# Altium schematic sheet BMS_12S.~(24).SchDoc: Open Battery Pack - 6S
size A3; Author: Morgane Vallée; Revision: 1.0; SheetNumber: 3; SheetTotal: 4
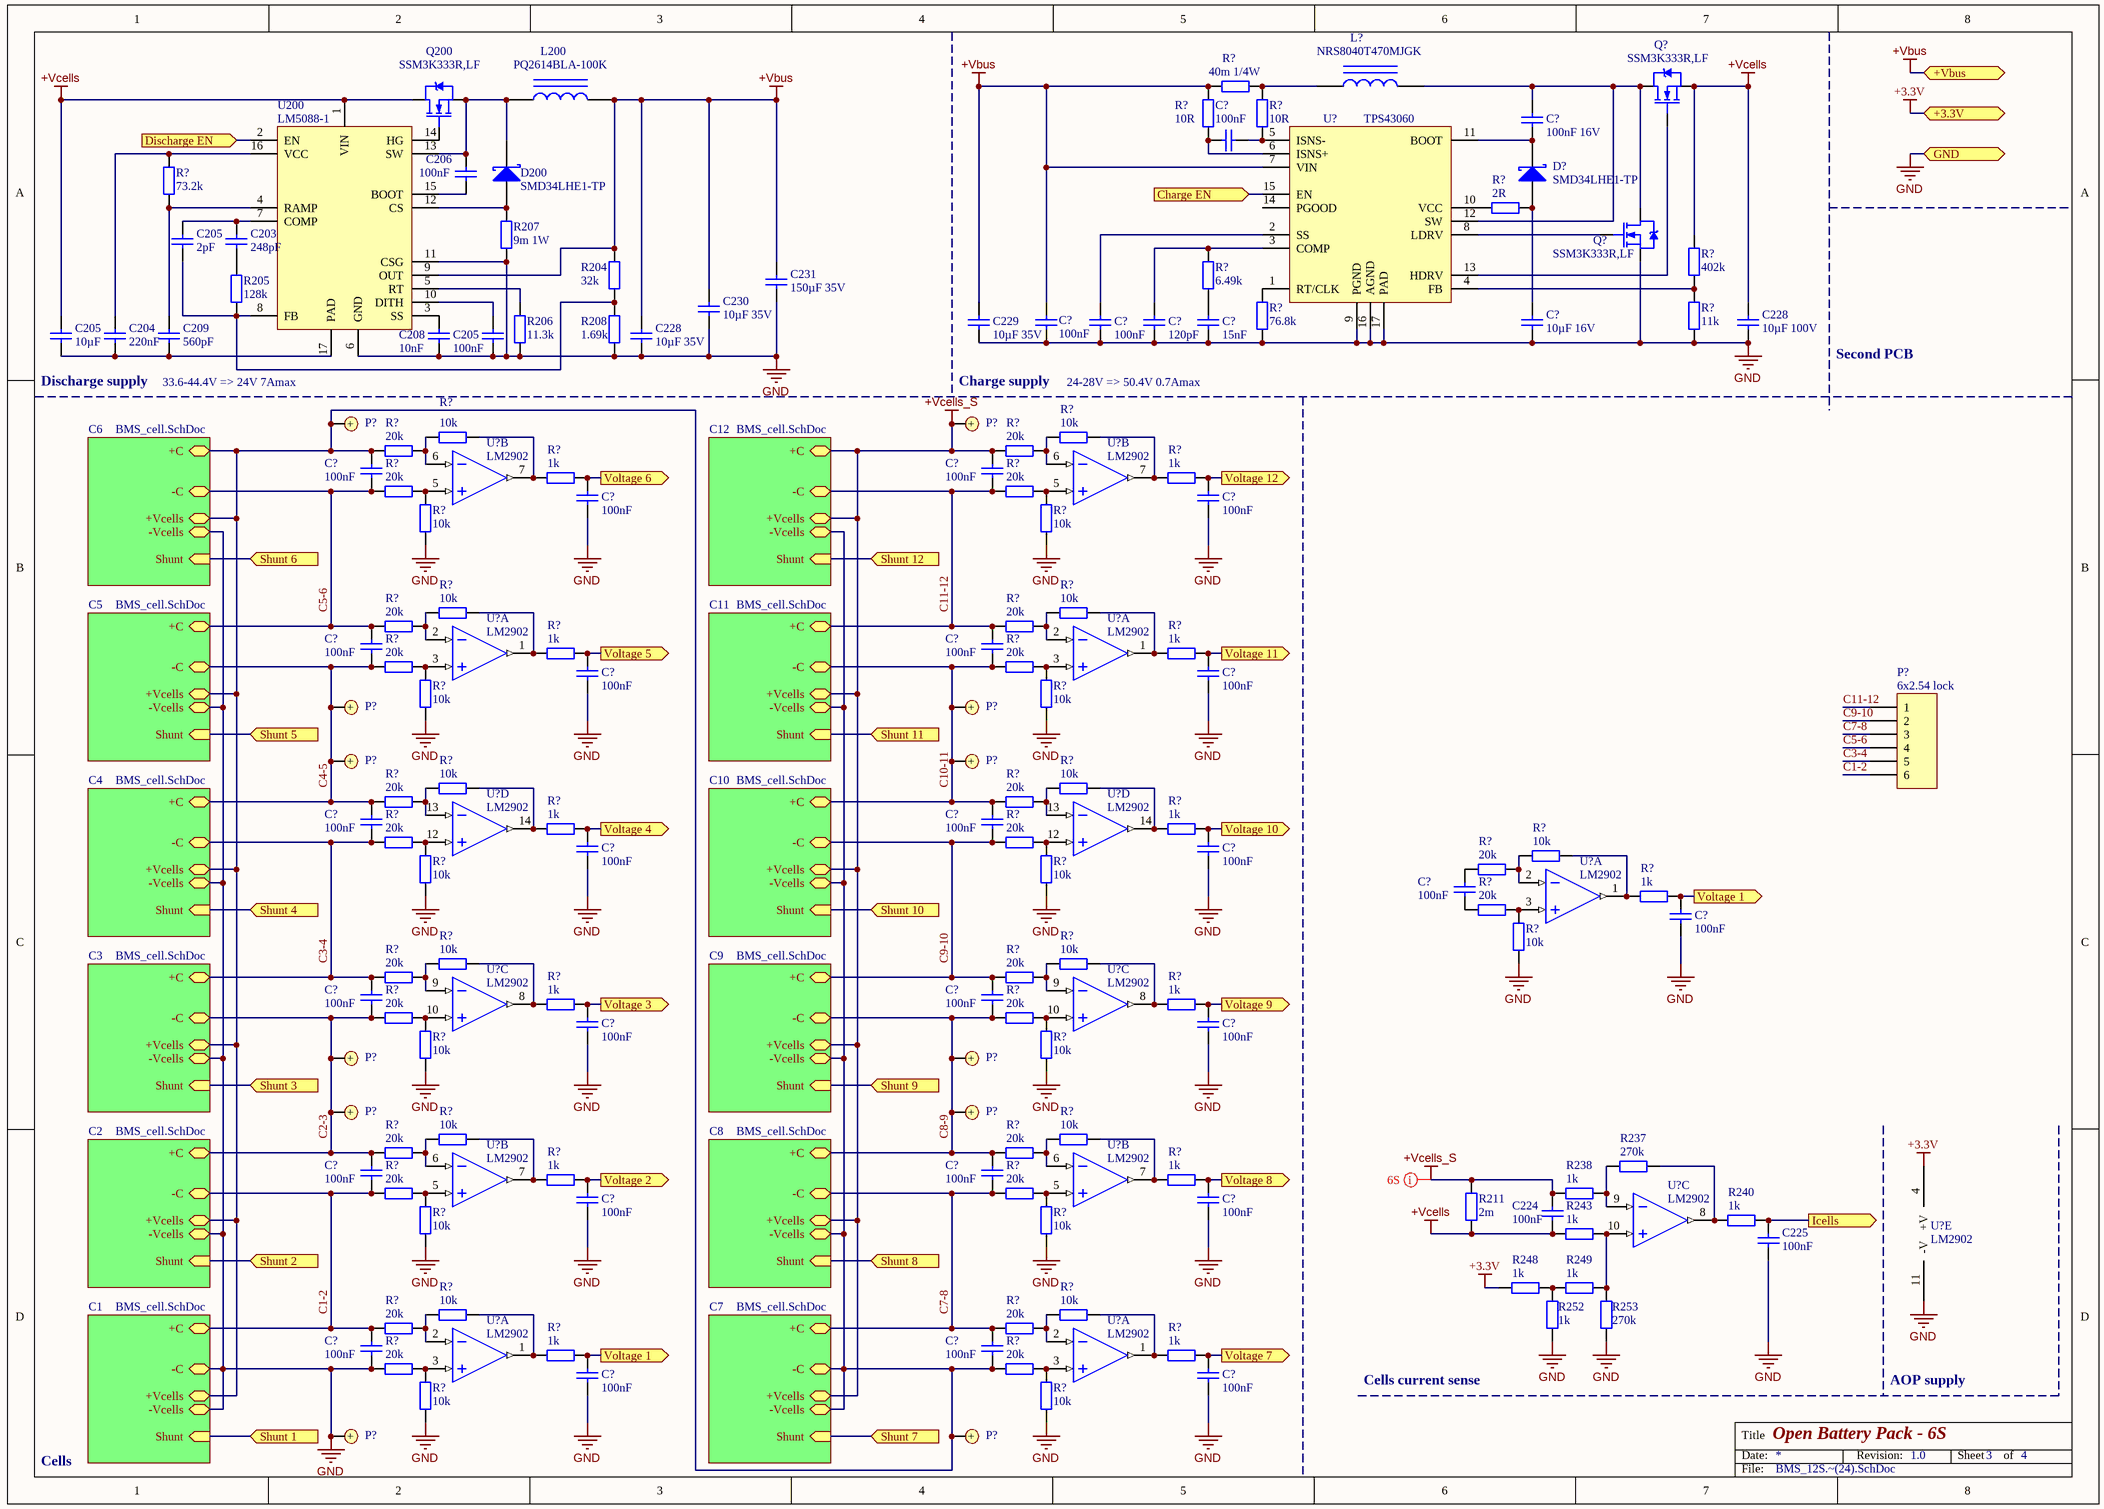
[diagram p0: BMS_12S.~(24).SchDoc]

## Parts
(Parts that share a designator on the sheet are numbered #1, #2 ... from top to bottom, then left to right.)
C203  248pF  [C0603]
C204  220nF  [C0603]
C205#1  2pF  [C0603]
C205#2  10µF  [C0603]
C205#3  100nF  [C0603]
C206  100nF  [C0603]
C208  10nF  [C0603]
C209  560pF  [C0603]
C224  100nF  [C0603]
C225  100nF  [C0603]
C228#1  10µF 100V  [C0603]
C228#2  10µF 35V  [C0603]
C229  10µF 35V  [C0603]
C230  10µF 35V  [C0603]
C231  150µF 35V  [C0603]
C?#1  100nF 16V  [C0603]
C?#2  100nF  [C0603]
C?#3  100nF  [C0603]
C?#4  120pF  [C0603]
C?#5  15nF  [C0603]
C?#6  10µF 16V  [C0805]
C?#7  100nF  [C0603]
C?#8  100nF  [C0603]
C?#9  100nF  [C0603]
C?#10  100nF  [C0603]
C?#11  100nF  [C0603]
C?#12  100nF  [C0603]
C?#13  100nF  [C0603]
C?#14  100nF  [C0603]
C?#15  100nF  [C0603]
C?#16  100nF  [C0603]
C?#17  100nF  [C0603]
C?#18  100nF  [C0603]
C?#19  100nF  [C0603]
C?#20  100nF  [C0603]
C?#21  100nF  [C0603]
C?#22  100nF  [C0603]
C?#23  100nF  [C0603]
C?#24  100nF  [C0603]
C?#25  100nF  [C0603]
C?#26  100nF  [C0603]
C?#27  100nF  [C0603]
C?#28  100nF  [C0603]
C?#29  100nF  [C0603]
C?#30  100nF  [C0603]
C?#31  100nF  [C0603]
C?#32  100nF  [C0603]
C?#33  100nF  [C0603]
D200  SMD34LHE1-TP  [SOD-123H]
D?  SMD34LHE1-TP  [SOD-123H]
L200  PQ2614BLA-100K  [SELF_SMD_8x8]
L?  NRS8040T470MJGK  [SELF_SMD_8x8]
P?#1  Bat+  [Keystone 241]  (value not drawn)
P?#2  Bat+  [Keystone 241]  (value not drawn)
P?#3  6x2.54 lock  [MOLEX KK 0022272061]
P?#4  Bat+  [Keystone 241]  (value not drawn)
P?#5  Bat+  [Keystone 241]  (value not drawn)
P?#6  Bat+  [Keystone 241]  (value not drawn)
P?#7  Bat+  [Keystone 241]  (value not drawn)
P?#8  Bat+  [Keystone 241]  (value not drawn)
P?#9  Bat+  [Keystone 241]  (value not drawn)
P?#10  Bat+  [Keystone 241]  (value not drawn)
P?#11  Bat+  [Keystone 241]  (value not drawn)
P?#12  Bat+  [Keystone 241]  (value not drawn)
P?#13  Bat+  [Keystone 241]  (value not drawn)
Q200  SSM3K333R,LF  [TI SOT-23-3 DBZ]
Q?#1  SSM3K333R,LF  [TI SOT-23-3 DBZ]
Q?#2  SSM3K333R,LF  [TI SOT-23-3 DBZ]
R204  32k  [R0603]
R205  128k  [R0603]
R206  11.3k  [R0603]
R207  9m 1W  [R1206]
R208  1.69k  [R0603]
R211  2m  [R1206]
R237  270k  [R0603]
R238  1k  [R0603]
R240  1k  [R0603]
R243  1k  [R0603]
R248  1k  [R0603]
R249  1k  [R0603]
R252  1k  [R0603]
R253  270k  [R0603]
R?#1  10R  [R0603]
R?#2  40m 1/4W  [R1206]
R?#3  10R  [R0603]
R?#4  73.2k  [R0603]
R?#5  2R  [R0603]
R?#6  402k  [R0603]
R?#7  6.49k  [R0603]
R?#8  76.8k  [R0603]
R?#9  11k  [R0603]
R?#10  10k  [R0603]
R?#11  10k  [R0603]
R?#12  20k  [R0603]
R?#13  20k  [R0603]
R?#14  1k  [R0603]
R?#15  1k  [R0603]
R?#16  20k  [R0603]
R?#17  10k  [R0603]
R?#18  20k  [R0603]
R?#19  10k  [R0603]
R?#20  10k  [R0603]
R?#21  10k  [R0603]
R?#22  20k  [R0603]
R?#23  20k  [R0603]
R?#24  1k  [R0603]
R?#25  1k  [R0603]
R?#26  20k  [R0603]
R?#27  10k  [R0603]
R?#28  20k  [R0603]
R?#29  10k  [R0603]
R?#30  10k  [R0603]
R?#31  10k  [R0603]
R?#32  20k  [R0603]
R?#33  20k  [R0603]
R?#34  1k  [R0603]
R?#35  1k  [R0603]
R?#36  10k  [R0603]
R?#37  20k  [R0603]
R?#38  10k  [R0603]
R?#39  20k  [R0603]
R?#40  10k  [R0603]
R?#41  20k  [R0603]
R?#42  1k  [R0603]
R?#43  20k  [R0603]
R?#44  10k  [R0603]
R?#45  10k  [R0603]
R?#46  10k  [R0603]
R?#47  20k  [R0603]
R?#48  20k  [R0603]
R?#49  1k  [R0603]
R?#50  1k  [R0603]
R?#51  20k  [R0603]
R?#52  10k  [R0603]
R?#53  20k  [R0603]
R?#54  10k  [R0603]
R?#55  10k  [R0603]
R?#56  10k  [R0603]
R?#57  20k  [R0603]
R?#58  20k  [R0603]
R?#59  1k  [R0603]
R?#60  1k  [R0603]
R?#61  20k  [R0603]
R?#62  10k  [R0603]
R?#63  20k  [R0603]
R?#64  10k  [R0603]
R?#65  10k  [R0603]
R?#66  10k  [R0603]
R?#67  20k  [R0603]
R?#68  20k  [R0603]
R?#69  1k  [R0603]
R?#70  1k  [R0603]
R?#71  20k  [R0603]
R?#72  10k  [R0603]
R?#73  20k  [R0603]
R?#74  10k  [R0603]
U200  LM5088-1  [TI MSOP-10 DGQ]
U?#1  TPS43060  [TI WQFN-16 RGH]
U?#2  LM2902  [Atmel SO-14 14S1]  (part B of 5)
U?#3  LM2902  [Atmel SO-14 14S1]  (part B of 5)
U?#4  LM2902  [Atmel SO-14 14S1]  (part A of 5)
U?#5  LM2902  [Atmel SO-14 14S1]  (part A of 5)
U?#6  LM2902  [Atmel SO-14 14S1]  (part D of 5)
U?#7  LM2902  [Atmel SO-14 14S1]  (part D of 5)
U?#8  LM2902  [Atmel SO-14 14S1]  (part A of 5)
U?#9  LM2902  [Atmel SO-14 14S1]  (part C of 5)
U?#10  LM2902  [Atmel SO-14 14S1]  (part C of 5)
U?#11  LM2902  [Atmel SO-14 14S1]  (part B of 5)
U?#12  LM2902  [Atmel SO-14 14S1]  (part B of 5)
U?#13  LM2902  [Atmel SO-14 14S1]  (part C of 5)
U?#14  LM2902  [Atmel SO-14 14S1]  (part E of 5)
U?#15  LM2902  [Atmel SO-14 14S1]  (part A of 5)
U?#16  LM2902  [Atmel SO-14 14S1]  (part A of 5)

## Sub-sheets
C1 = BMS_cell.SchDoc: -C, +C, +Vcells, -Vcells, Shunt (in)
C2 = BMS_cell.SchDoc: -C, +C, +Vcells, -Vcells, Shunt (in)
C3 = BMS_cell.SchDoc: -C, +C, +Vcells, -Vcells, Shunt (in)
C4 = BMS_cell.SchDoc: -C, +C, +Vcells, -Vcells, Shunt (in)
C5 = BMS_cell.SchDoc: -C, +C, +Vcells, -Vcells, Shunt (in)
C6 = BMS_cell.SchDoc: -C, +C, +Vcells, -Vcells, Shunt (in)
C7 = BMS_cell.SchDoc: -C, +C, +Vcells, -Vcells, Shunt (in)
C8 = BMS_cell.SchDoc: -C, +C, +Vcells, -Vcells, Shunt (in)
C9 = BMS_cell.SchDoc: -C, +C, +Vcells, -Vcells, Shunt (in)
C10 = BMS_cell.SchDoc: -C, +C, +Vcells, -Vcells, Shunt (in)
C11 = BMS_cell.SchDoc: -C, +C, +Vcells, -Vcells, Shunt (in)
C12 = BMS_cell.SchDoc: -C, +C, +Vcells, -Vcells, Shunt (in)

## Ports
+3.3V, +Vbus, Charge EN (in), Discharge EN (in), GND, Icells (out), Shunt 1 (in), Shunt 2 (in), Shunt 3 (in), Shunt 4 (in), Shunt 5 (in), Shunt 6 (in), Shunt 7 (in), Shunt 8 (in), Shunt 9 (in), Shunt 10 (in), Shunt 11 (in), Shunt 12 (in), Voltage 1 (out), Voltage 2 (out), Voltage 3 (out), Voltage 4 (out), Voltage 5 (out), Voltage 6 (out), Voltage 7 (out), Voltage 8 (out), Voltage 9 (out), Voltage 10 (out), Voltage 11 (out), Voltage 12 (out)

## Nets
+3.3V: R248.2 U?#14.4(+V) ; port +3.3V
+Vbus: C228#2.1 C229.1 C230.1 C231.1 C?#7.2 L200.2 R204.2 R?#1.1 R?#2.2 U200.9(OUT) U?#1.7(VIN) ; port +Vbus
+Vcells: C205#2.1 C224.2 C228#1.1 Q200.3(D) Q?#1.2(S) R211.1 R243.2 R?#6.2 U200.1(VIN)
+Vcells_S: C224.1 C?#9.1 P?#2.1 R211.2 R238.1 R?#13.1 ; sheet C7/+Vcells, sheet C8/+Vcells, sheet C9/+Vcells, sheet C10/+Vcells, sheet C11/+Vcells, sheet C12/+C, sheet C12/+Vcells
GND: C205#3.2 C208.2 C225.2 C228#1.2 C228#2.2 C229.2 C230.2 C231.2 C?#3.2 C?#4.2 C?#5.2 C?#6.2 C?#7.1 C?#10.2 C?#11.2 C?#14.2 C?#15.2 C?#18.2 C?#19.2 C?#21.2 C?#24.2 C?#25.2 C?#28.2 C?#29.2 C?#30.2 C?#32.2 C?#33.2 P?#12.1 Q?#2.2(S) R206.1 R207.1 R208.1 R252.2 R253.1 R?#8.1 R?#9.1 R?#17.2 R?#19.2 R?#27.2 R?#29.2 R?#38.2 R?#40.2 R?#44.2 R?#52.2 R?#54.2 R?#62.2 R?#64.2 R?#71.2 R?#72.2 R?#74.2 U200.6(GND) U200.11(CSG) U?#1.9(PGND) U?#1.16(AGND) U?#1.17(PAD) U?#14.11(-V) ; port GND, sheet C1/-C, sheet C1/-Vcells, sheet C2/-Vcells, sheet C3/-Vcells, sheet C4/-Vcells, sheet C5/-Vcells, sheet C6/-Vcells
C1-2: C?#26.2 C?#30.1 P?#3.6 R?#61.2 R?#67.1 ; sheet C1/+C, sheet C2/-C
C2-3: C?#22.2 C?#26.1 P?#8.1 P?#10.1 R?#51.2 R?#57.1 ; sheet C2/+C, sheet C3/-C
C3-4: C?#16.2 C?#22.1 P?#3.5 R?#37.2 R?#47.1 ; sheet C3/+C, sheet C4/-C
C4-5: C?#12.2 C?#16.1 P?#4.1 P?#6.1 R?#26.2 R?#32.1 ; sheet C4/+C, sheet C5/-C
C5-6: C?#8.2 C?#12.1 P?#3.4 R?#16.2 R?#22.1 ; sheet C5/+C, sheet C6/-C
C7-8: C?#27.2 C?#31.1 P?#3.3 R?#63.2 R?#68.1 ; sheet C7/+C, sheet C8/-C
C8-9: C?#23.2 C?#27.1 P?#9.1 P?#11.1 R?#53.2 R?#58.1 ; sheet C8/+C, sheet C9/-C
C9-10: C?#17.2 C?#23.1 P?#3.2 R?#39.2 R?#48.1 ; sheet C9/+C, sheet C10/-C
C10-11: C?#13.2 C?#17.1 P?#5.1 P?#7.1 R?#28.2 R?#33.1 ; sheet C10/+C, sheet C11/-C
C11-12: C?#9.2 C?#13.1 P?#3.1 R?#18.2 R?#23.1 ; sheet C11/+C, sheet C12/-C
Charge EN: U?#1.15(EN) ; port Charge EN
Discharge EN: U200.2(EN) ; port Discharge EN
Icells: C225.1 R240.1 ; port Icells
Shunt 1: port Shunt 1, sheet C1/Shunt
Shunt 2: port Shunt 2, sheet C2/Shunt
Shunt 3: port Shunt 3, sheet C3/Shunt
Shunt 4: port Shunt 4, sheet C4/Shunt
Shunt 5: port Shunt 5, sheet C5/Shunt
Shunt 6: port Shunt 6, sheet C6/Shunt
Shunt 7: port Shunt 7, sheet C7/Shunt
Shunt 8: port Shunt 8, sheet C8/Shunt
Shunt 9: port Shunt 9, sheet C9/Shunt
Shunt 10: port Shunt 10, sheet C10/Shunt
Shunt 11: port Shunt 11, sheet C11/Shunt
Shunt 12: port Shunt 12, sheet C12/Shunt
Voltage 1: C?#21.1 C?#32.1 R?#42.1 R?#69.1 ; port Voltage 1
Voltage 2: C?#28.1 R?#59.1 ; port Voltage 2
Voltage 3: C?#24.1 R?#49.1 ; port Voltage 3
Voltage 4: C?#18.1 R?#34.1 ; port Voltage 4
Voltage 5: C?#14.1 R?#24.1 ; port Voltage 5
Voltage 6: C?#10.1 R?#14.1 ; port Voltage 6
Voltage 7: C?#33.1 R?#70.1 ; port Voltage 7
Voltage 8: C?#29.1 R?#60.1 ; port Voltage 8
Voltage 9: C?#25.1 R?#50.1 ; port Voltage 9
Voltage 10: C?#19.1 R?#35.1 ; port Voltage 10
Voltage 11: C?#15.1 R?#25.1 ; port Voltage 11
Voltage 12: C?#11.1 R?#15.1 ; port Voltage 12
NetC203_1: C203.1 C205#1.1 U200.7(COMP)
NetC203_2: C203.2 R205.2
NetC204_1: C204.1 R?#4.2 U200.16(VCC)
NetC204_2: C204.2 C205#2.2 C209.2 U200.17(PAD)
NetC205#1_2: C205#1.2 R204.1 R205.1 R208.2 U200.8(FB)
NetC205#3_1: C205#3.1 U200.10(DITH)
NetC206_1: C206.1 D200.3(K) L200.1 Q200.2(S) U200.13(SW)
NetC206_2: C206.2 U200.15(BOOT)
NetC208_1: C208.1 U200.3(SS)
NetC209_1: C209.1 R?#4.1 U200.4(RAMP)
NetC?#1_1: C?#1.1 L?.2 Q?#1.3(D) Q?#2.3(D) U?#1.12(SW)
NetC?#1_2: C?#1.2 D?.3(K) U?#1.11(BOOT)
NetC?#2_1: C?#2.1 R?#3.2 U?#1.5(ISNS-)
NetC?#2_2: C?#2.2 R?#1.2 U?#1.6(ISNS+)
NetC?#3_1: C?#3.1 U?#1.2(SS)
NetC?#4_1: C?#4.1 R?#7.2 U?#1.3(COMP)
NetC?#5_1: C?#5.1 R?#7.1
NetC?#6_1: C?#6.1 D?.1(A) R?#5.1
NetC?#8_1: C?#8.1 C?#31.2 P?#1.1 P?#13.1 R?#12.1 R?#73.2 ; sheet C1/+Vcells, sheet C2/+Vcells, sheet C3/+Vcells, sheet C4/+Vcells, sheet C5/+Vcells, sheet C6/+C, sheet C6/+Vcells, sheet C7/-C, sheet C7/-Vcells, sheet C8/-Vcells, sheet C9/-Vcells, sheet C10/-Vcells, sheet C11/-Vcells, sheet C12/-Vcells
NetC?#20_1: C?#20.1 R?#41.1
NetC?#20_2: C?#20.2 R?#43.2
NetD200_1: D200.1(A) R207.2 U200.12(CS)
NetL?_1: L?.1 R?#2.1 R?#3.1
NetQ200_1: Q200.1(G) U200.14(HG)
NetQ?#1_1: Q?#1.1(G) U?#1.13(HDRV)
NetQ?#2_1: Q?#2.1(G) U?#1.8(LDRV)
NetR206_2: R206.2 U200.5(RT)
NetR237_1: R237.1 R240.2 U?#13.8(OUT)
NetR237_2: R237.2 R238.2 U?#13.9(IN-)
NetR243_1: R243.1 R249.1 R253.2 U?#13.10(IN+)
NetR248_1: R248.1 R249.2 R252.1
NetR?#5_2: R?#5.2 U?#1.10(VCC)
NetR?#6_1: R?#6.1 R?#9.2 U?#1.4(FB)
NetR?#8_2: R?#8.2 U?#1.1(RT/CLK)
NetR?#10_1: R?#10.1 R?#12.2 U?#2.6(IN-)
NetR?#10_2: R?#10.2 R?#14.2 U?#2.7(OUT)
NetR?#11_1: R?#11.1 R?#13.2 U?#3.6(IN-)
NetR?#11_2: R?#11.2 R?#15.2 U?#3.7(OUT)
NetR?#16_1: R?#16.1 R?#17.1 U?#2.5(IN+)
NetR?#18_1: R?#18.1 R?#19.1 U?#3.5(IN+)
NetR?#20_1: R?#20.1 R?#22.2 U?#4.2(IN-)
NetR?#20_2: R?#20.2 R?#24.2 U?#4.1(OUT)
NetR?#21_1: R?#21.1 R?#23.2 U?#5.2(IN-)
NetR?#21_2: R?#21.2 R?#25.2 U?#5.1(OUT)
NetR?#26_1: R?#26.1 R?#27.1 U?#4.3(IN+)
NetR?#28_1: R?#28.1 R?#29.1 U?#5.3(IN+)
NetR?#30_1: R?#30.1 R?#32.2 U?#6.13(IN-)
NetR?#30_2: R?#30.2 R?#34.2 U?#6.14(OUT)
NetR?#31_1: R?#31.1 R?#33.2 U?#7.13(IN-)
NetR?#31_2: R?#31.2 R?#35.2 U?#7.14(OUT)
NetR?#36_1: R?#36.1 R?#41.2 U?#8.2(IN-)
NetR?#36_2: R?#36.2 R?#42.2 U?#8.1(OUT)
NetR?#37_1: R?#37.1 R?#38.1 U?#6.12(IN+)
NetR?#39_1: R?#39.1 R?#40.1 U?#7.12(IN+)
NetR?#43_1: R?#43.1 R?#44.1 U?#8.3(IN+)
NetR?#45_1: R?#45.1 R?#47.2 U?#9.9(IN-)
NetR?#45_2: R?#45.2 R?#49.2 U?#9.8(OUT)
NetR?#46_1: R?#46.1 R?#48.2 U?#10.9(IN-)
NetR?#46_2: R?#46.2 R?#50.2 U?#10.8(OUT)
NetR?#51_1: R?#51.1 R?#52.1 U?#9.10(IN+)
NetR?#53_1: R?#53.1 R?#54.1 U?#10.10(IN+)
NetR?#55_1: R?#55.1 R?#57.2 U?#11.6(IN-)
NetR?#55_2: R?#55.2 R?#59.2 U?#11.7(OUT)
NetR?#56_1: R?#56.1 R?#58.2 U?#12.6(IN-)
NetR?#56_2: R?#56.2 R?#60.2 U?#12.7(OUT)
NetR?#61_1: R?#61.1 R?#62.1 U?#11.5(IN+)
NetR?#63_1: R?#63.1 R?#64.1 U?#12.5(IN+)
NetR?#65_1: R?#65.1 R?#67.2 U?#15.2(IN-)
NetR?#65_2: R?#65.2 R?#69.2 U?#15.1(OUT)
NetR?#66_1: R?#66.1 R?#68.2 U?#16.2(IN-)
NetR?#66_2: R?#66.2 R?#70.2 U?#16.1(OUT)
NetR?#71_1: R?#71.1 R?#72.1 U?#15.3(IN+)
NetR?#73_1: R?#73.1 R?#74.1 U?#16.3(IN+)

Not connected (* = marked no-connect by the designer): U?#1 14(PGOOD)

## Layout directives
net class 6S: +Vcells_S

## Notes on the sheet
- Second PCB
- Discharge supply
- 33.6-44.4V => 24V 7Amax
- Charge supply
- (near C?#4) 24-28V => 50.4V 0.7Amax
- Cells current sense
- AOP supply
- Cells

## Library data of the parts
C203 C204 C205#1-C205#3 C206 C208 C209 C224 C225 C228#1 C228#2 C229-C231 C?#1-C?#33 = Cap: Capacitor
D200 D? = Diode BAT17
L200 L? = Inductor Iron: Magnetic-Core Inductor
P?#1 P?#2 P?#4-P?#13 = Bat+: Battery contact +
P?#3 = Header 6: Header, 6-Pin
Q200 Q?#1 Q?#2 = MOSFET_N
R204-R208 R211 R237 R238 R240 R243 R248 R249 R252 R253 R?#1-R?#74 = Res2: Resistor
U200 = LM5088-1: Wide Input Range Non-Synchronous Buck Controller
U?#1 = TPS43060: Low Quiescent Current Synchronous Boost  DC-DC Controller With Wide VIN Range
U?#2-U?#16 = LM2902: Low-power quad operational amplifiers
